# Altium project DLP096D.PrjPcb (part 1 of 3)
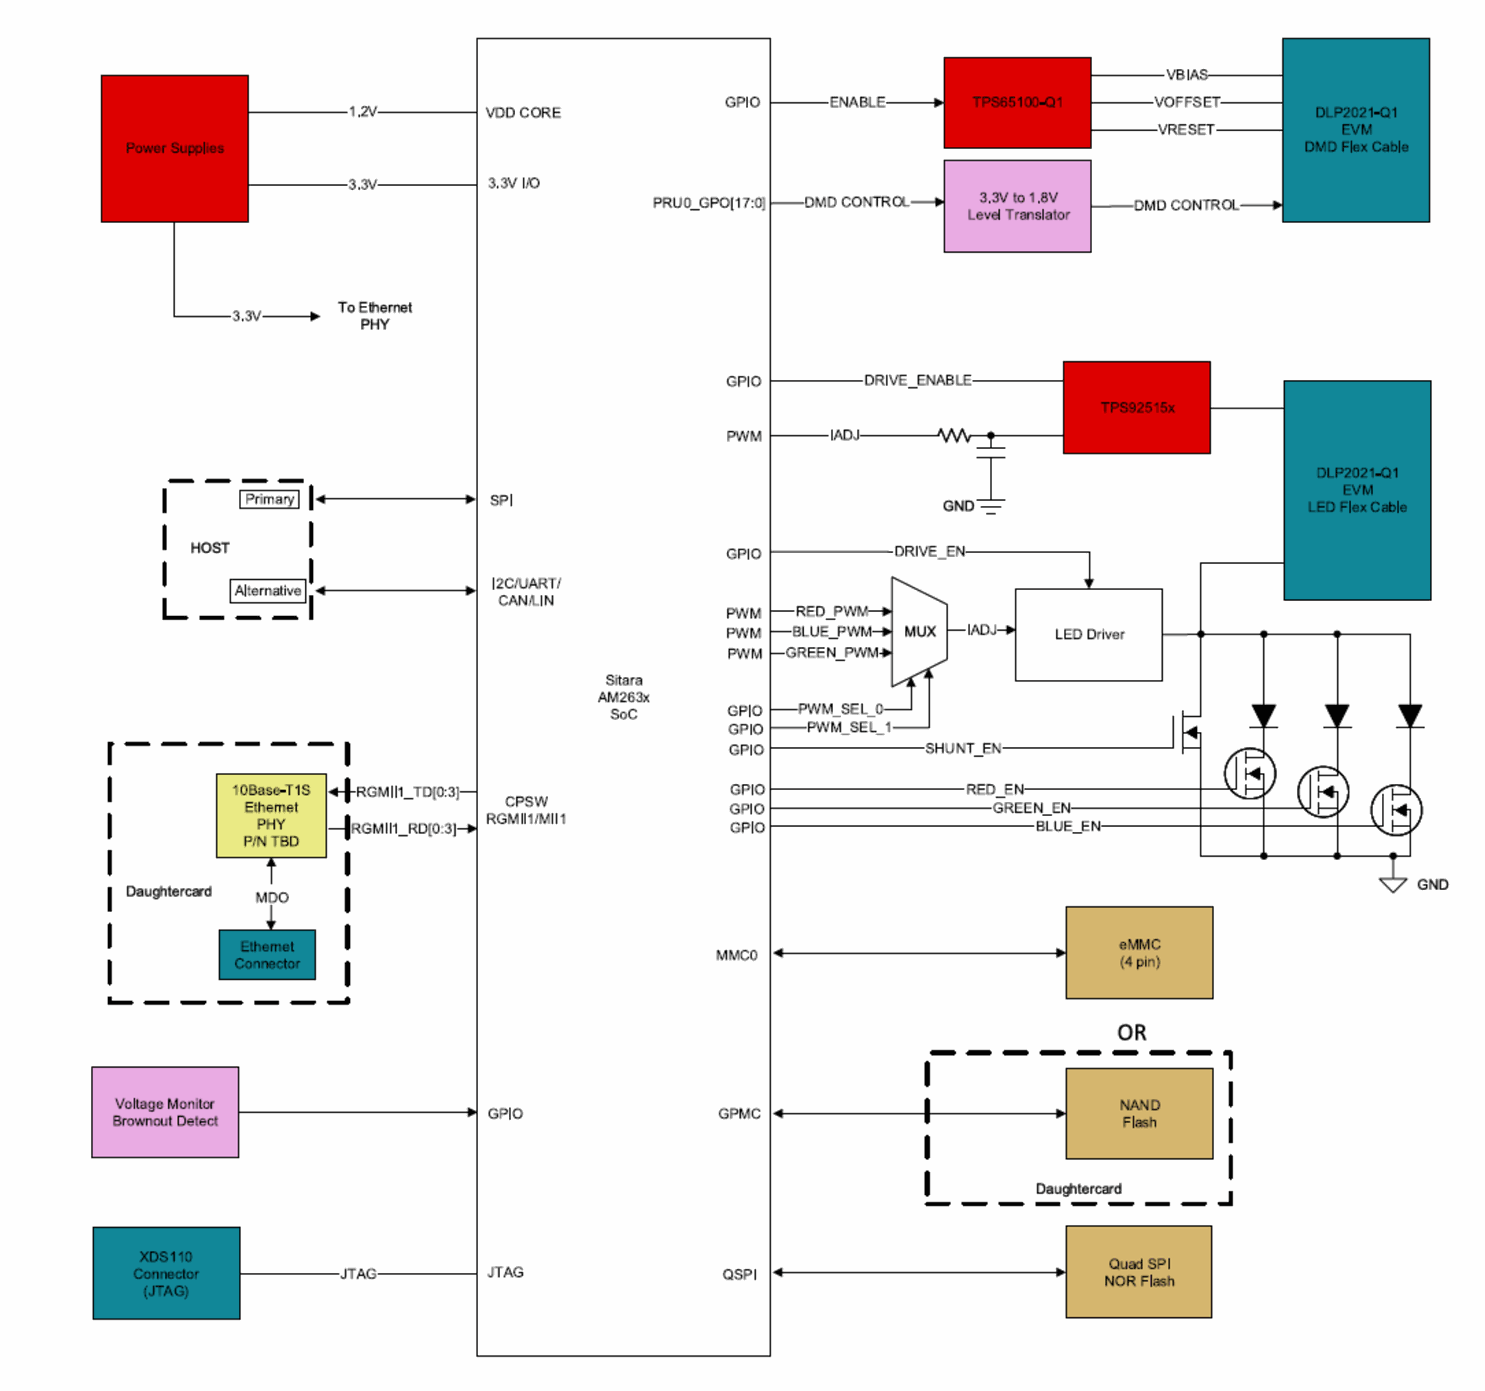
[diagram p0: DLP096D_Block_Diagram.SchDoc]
TID: N/A; TechSupport: http://www.ti.com/support; SCH_Rev: D; PRJ_Title: DLP2021AM263Q1EVM; PRJ_Number: DLP096; PRJ_Engineer: A. Whitehead; PRJ_Customer: Public Release; PCB_Rev: D; PCB_Layout: A. Whitehead; EVM_Orderable: DLP2021AM263Q1EVM; DrawnByGlobal: A. Whitehead; CopyrightYear: 2026
10 sheets, 329 parts. Net scope: global (net labels, ports and power ports of the same name join across sheets).
Board file: DLP096D.PcbDoc
Sheets:
  DLP096D_Block_Diagram.SchDoc
  DLP096D_Power_Tree.SchDoc
  DLP096D_System_Power.SchDoc
  DLP096D_SoC_Power_Clock.SchDoc
  DLP096D_DMD_Power.SchDoc
  DLP096D_DMD_Interface.SchDoc
  DLP096D_SoC_Memory.SchDoc
  DLP096D_Interfaces_Sockets.SchDoc
  DLP096D_LED_Driver.SchDoc
  DLP096D_Hardware.SchDoc

## Sheet DLP096D_Block_Diagram.SchDoc: Block Diagram
size 431 x 279 mm; Date: Not shown in title block; ApprovedBy: Not shown in title block; CheckedBy: Not shown in title block; Author: Not shown in title block; CompanyName: Not shown in title block; DrawnBy: A. Whitehead; Engineer: Not shown in title block; Organization: Not shown in title block; Address1: Not shown in title block; Address2: Not shown in title block; Address3: Not shown in title block; Address4: Not shown in title block; DocumentNumber: 1; Revision: Use project parameter SCH_Rev; SheetNumber: 1; SheetTotal: 10; PageSetup: Record=PageOptions¦CenterHorizontal=True¦CenterVertical=True¦PrintScale=1.00¦XCorrection=1.00¦YCorrection=1.00¦PrintKind=0¦BorderSize=5000000¦LeftOffset=0¦BottomOffset=0¦Orientation=2¦PaperLength=1000¦PaperWidth=1000¦Scale=100¦PaperSource=15¦PrintQuality=600¦MediaType=1¦DitherType=10¦PaperKind=Letter¦PrintScaleMode=1

## Sheet DLP096D_Power_Tree.SchDoc: Power Tree
size 431 x 279 mm; Date: Not shown in title block; ApprovedBy: Not shown in title block; CheckedBy: Not shown in title block; Author: Not shown in title block; CompanyName: Not shown in title block; DrawnBy: A. Whitehead; Engineer: Not shown in title block; Organization: Not shown in title block; Address1: Not shown in title block; Address2: Not shown in title block; Address3: Not shown in title block; Address4: Not shown in title block; DocumentNumber: 2; Revision: Use project parameter SCH_Rev; SheetNumber: 2; SheetTotal: 10; PageSetup: Record=PageOptions¦CenterHorizontal=True¦CenterVertical=True¦PrintScale=1.00¦XCorrection=1.00¦YCorrection=1.00¦PrintKind=0¦BorderSize=5000000¦LeftOffset=0¦BottomOffset=0¦Orientation=2¦PaperLength=1000¦PaperWidth=1000¦Scale=100¦PaperSource=15¦PrintQuality=600¦MediaType=1¦DitherType=10¦PaperKind=Letter¦PrintScaleMode=1
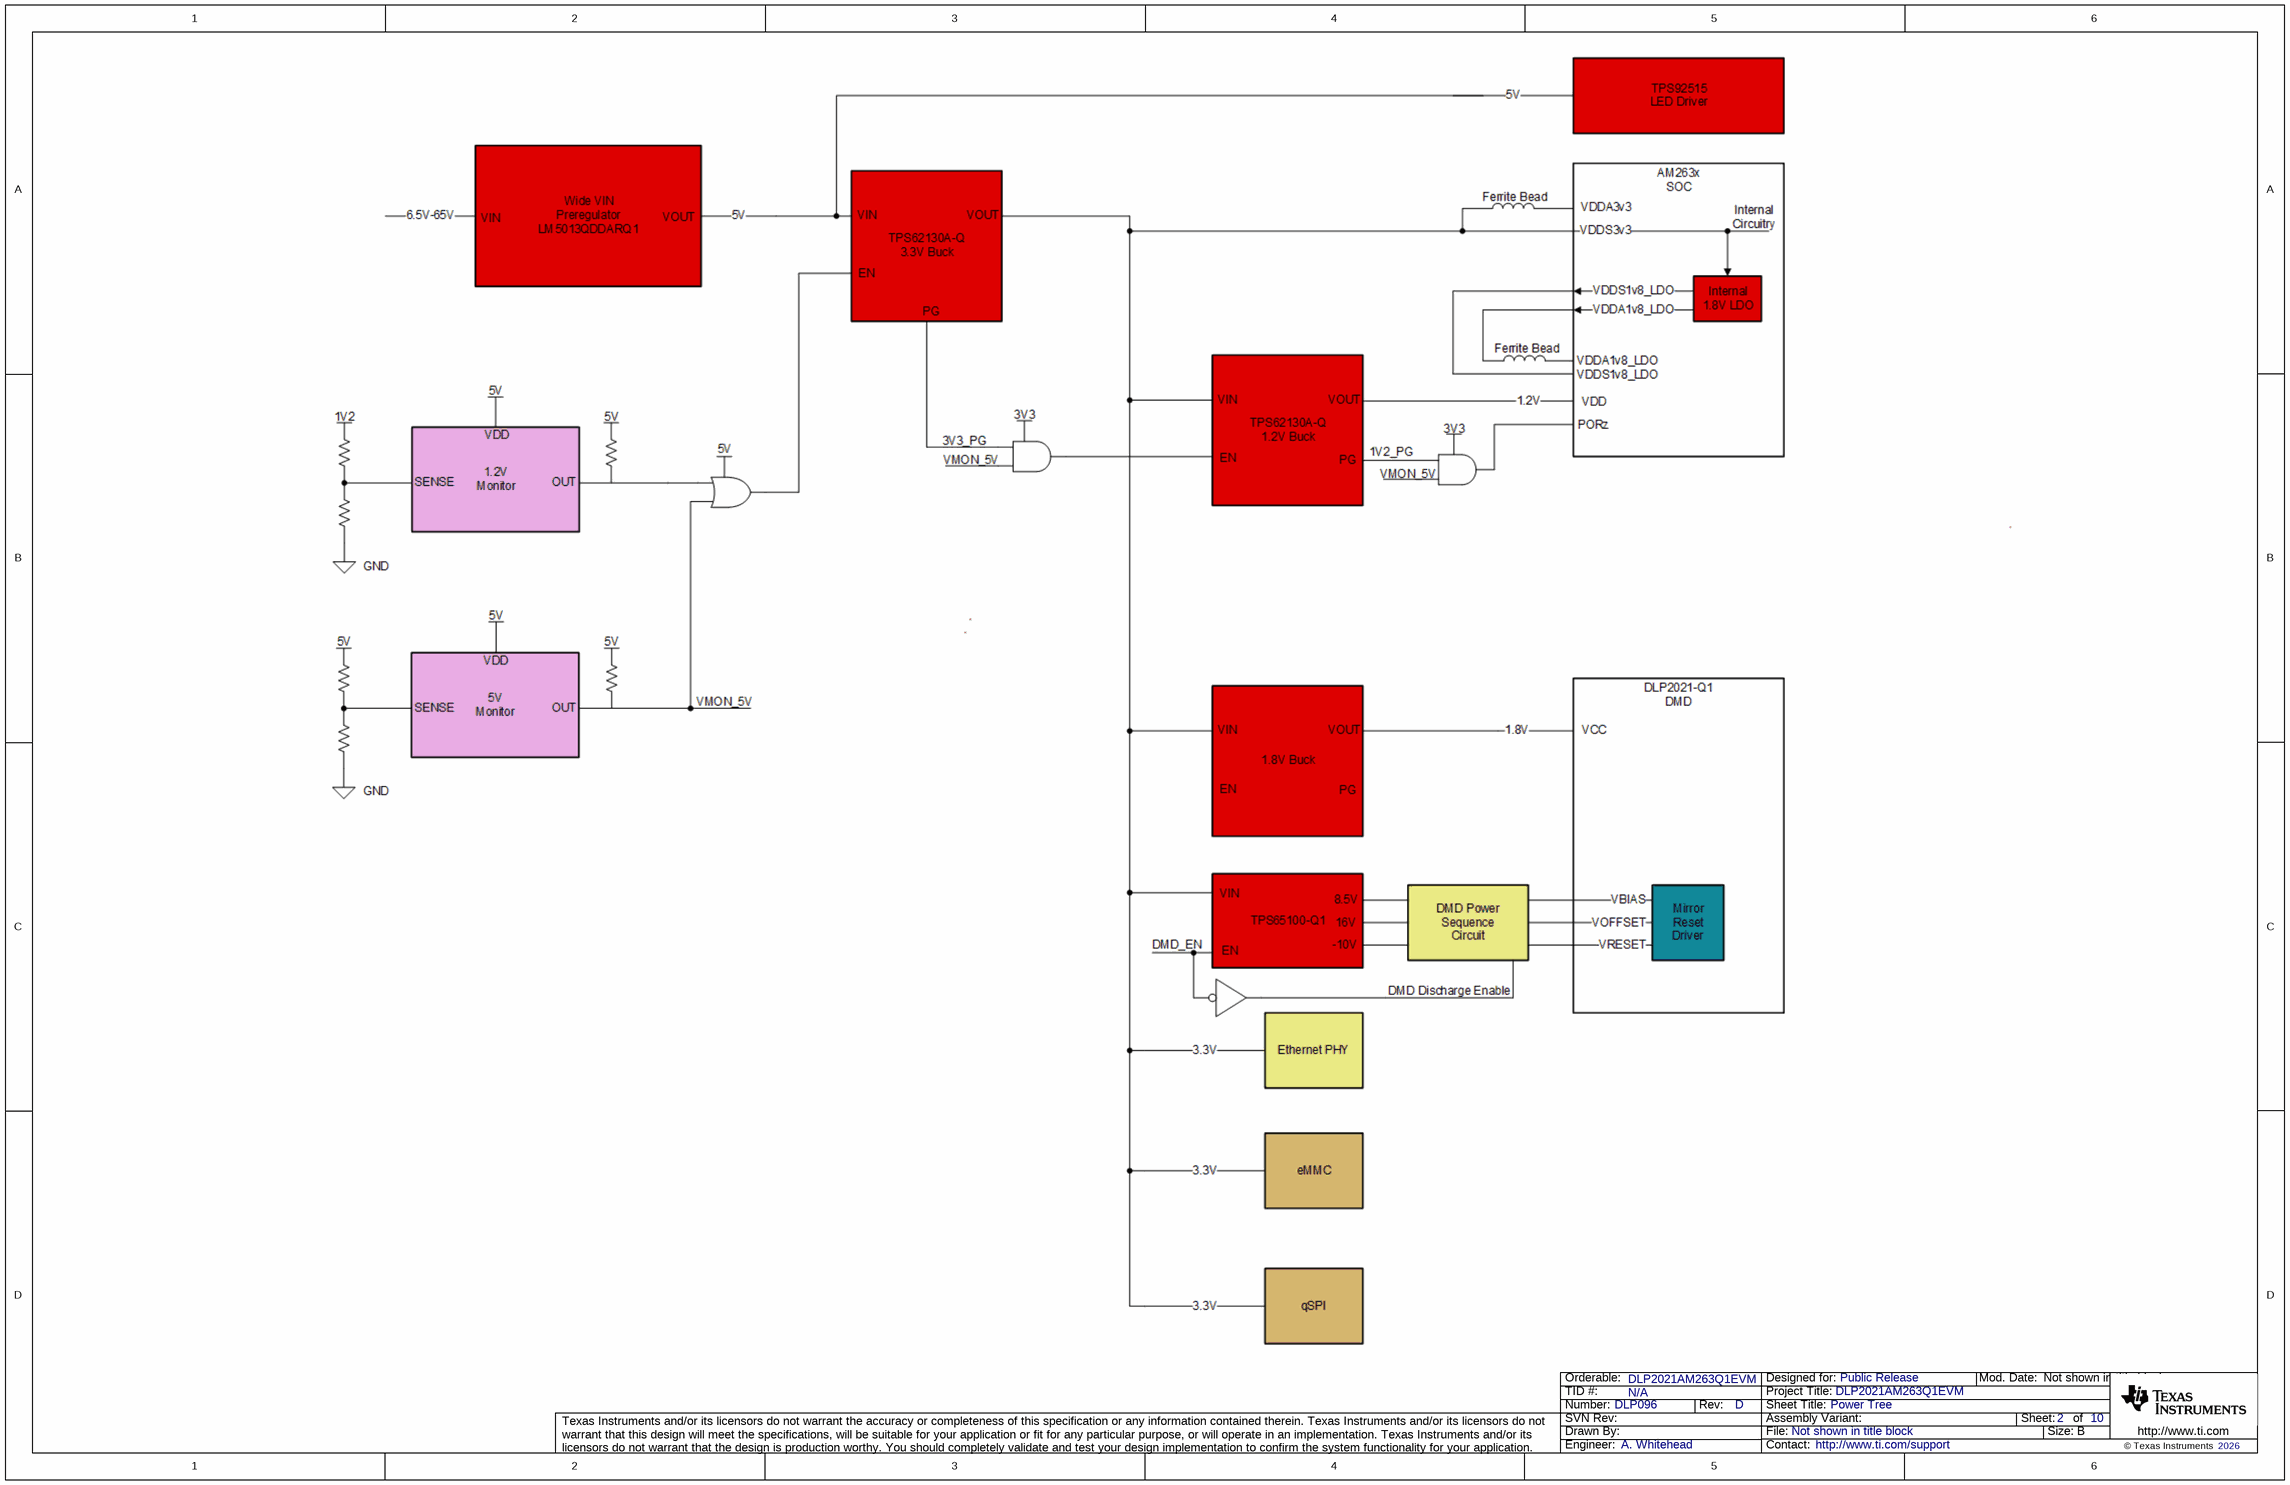
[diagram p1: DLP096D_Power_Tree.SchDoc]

## Sheet DLP096D_System_Power.SchDoc: System_Power
size 431 x 279 mm; Date: Not shown in title block; ApprovedBy: Not shown in title block; CheckedBy: Not shown in title block; Author: Not shown in title block; CompanyName: Not shown in title block; DrawnBy: A. Whitehead; Engineer: Not shown in title block; Organization: Not shown in title block; Address1: Not shown in title block; Address2: Not shown in title block; Address3: Not shown in title block; Address4: Not shown in title block; DocumentNumber: 3; Revision: Use project parameter SCH_Rev; SheetNumber: 3; SheetTotal: 10; PageSetup: Record=PageOptions¦CenterHorizontal=True¦CenterVertical=True¦PrintScale=1.00¦XCorrection=1.00¦YCorrection=1.00¦PrintKind=0¦BorderSize=5000000¦LeftOffset=0¦BottomOffset=0¦Orientation=2¦PaperLength=1000¦PaperWidth=1000¦Scale=100¦PaperSource=15¦PrintQuality=600¦MediaType=1¦DitherType=10¦PaperKind=Letter¦PrintScaleMode=1
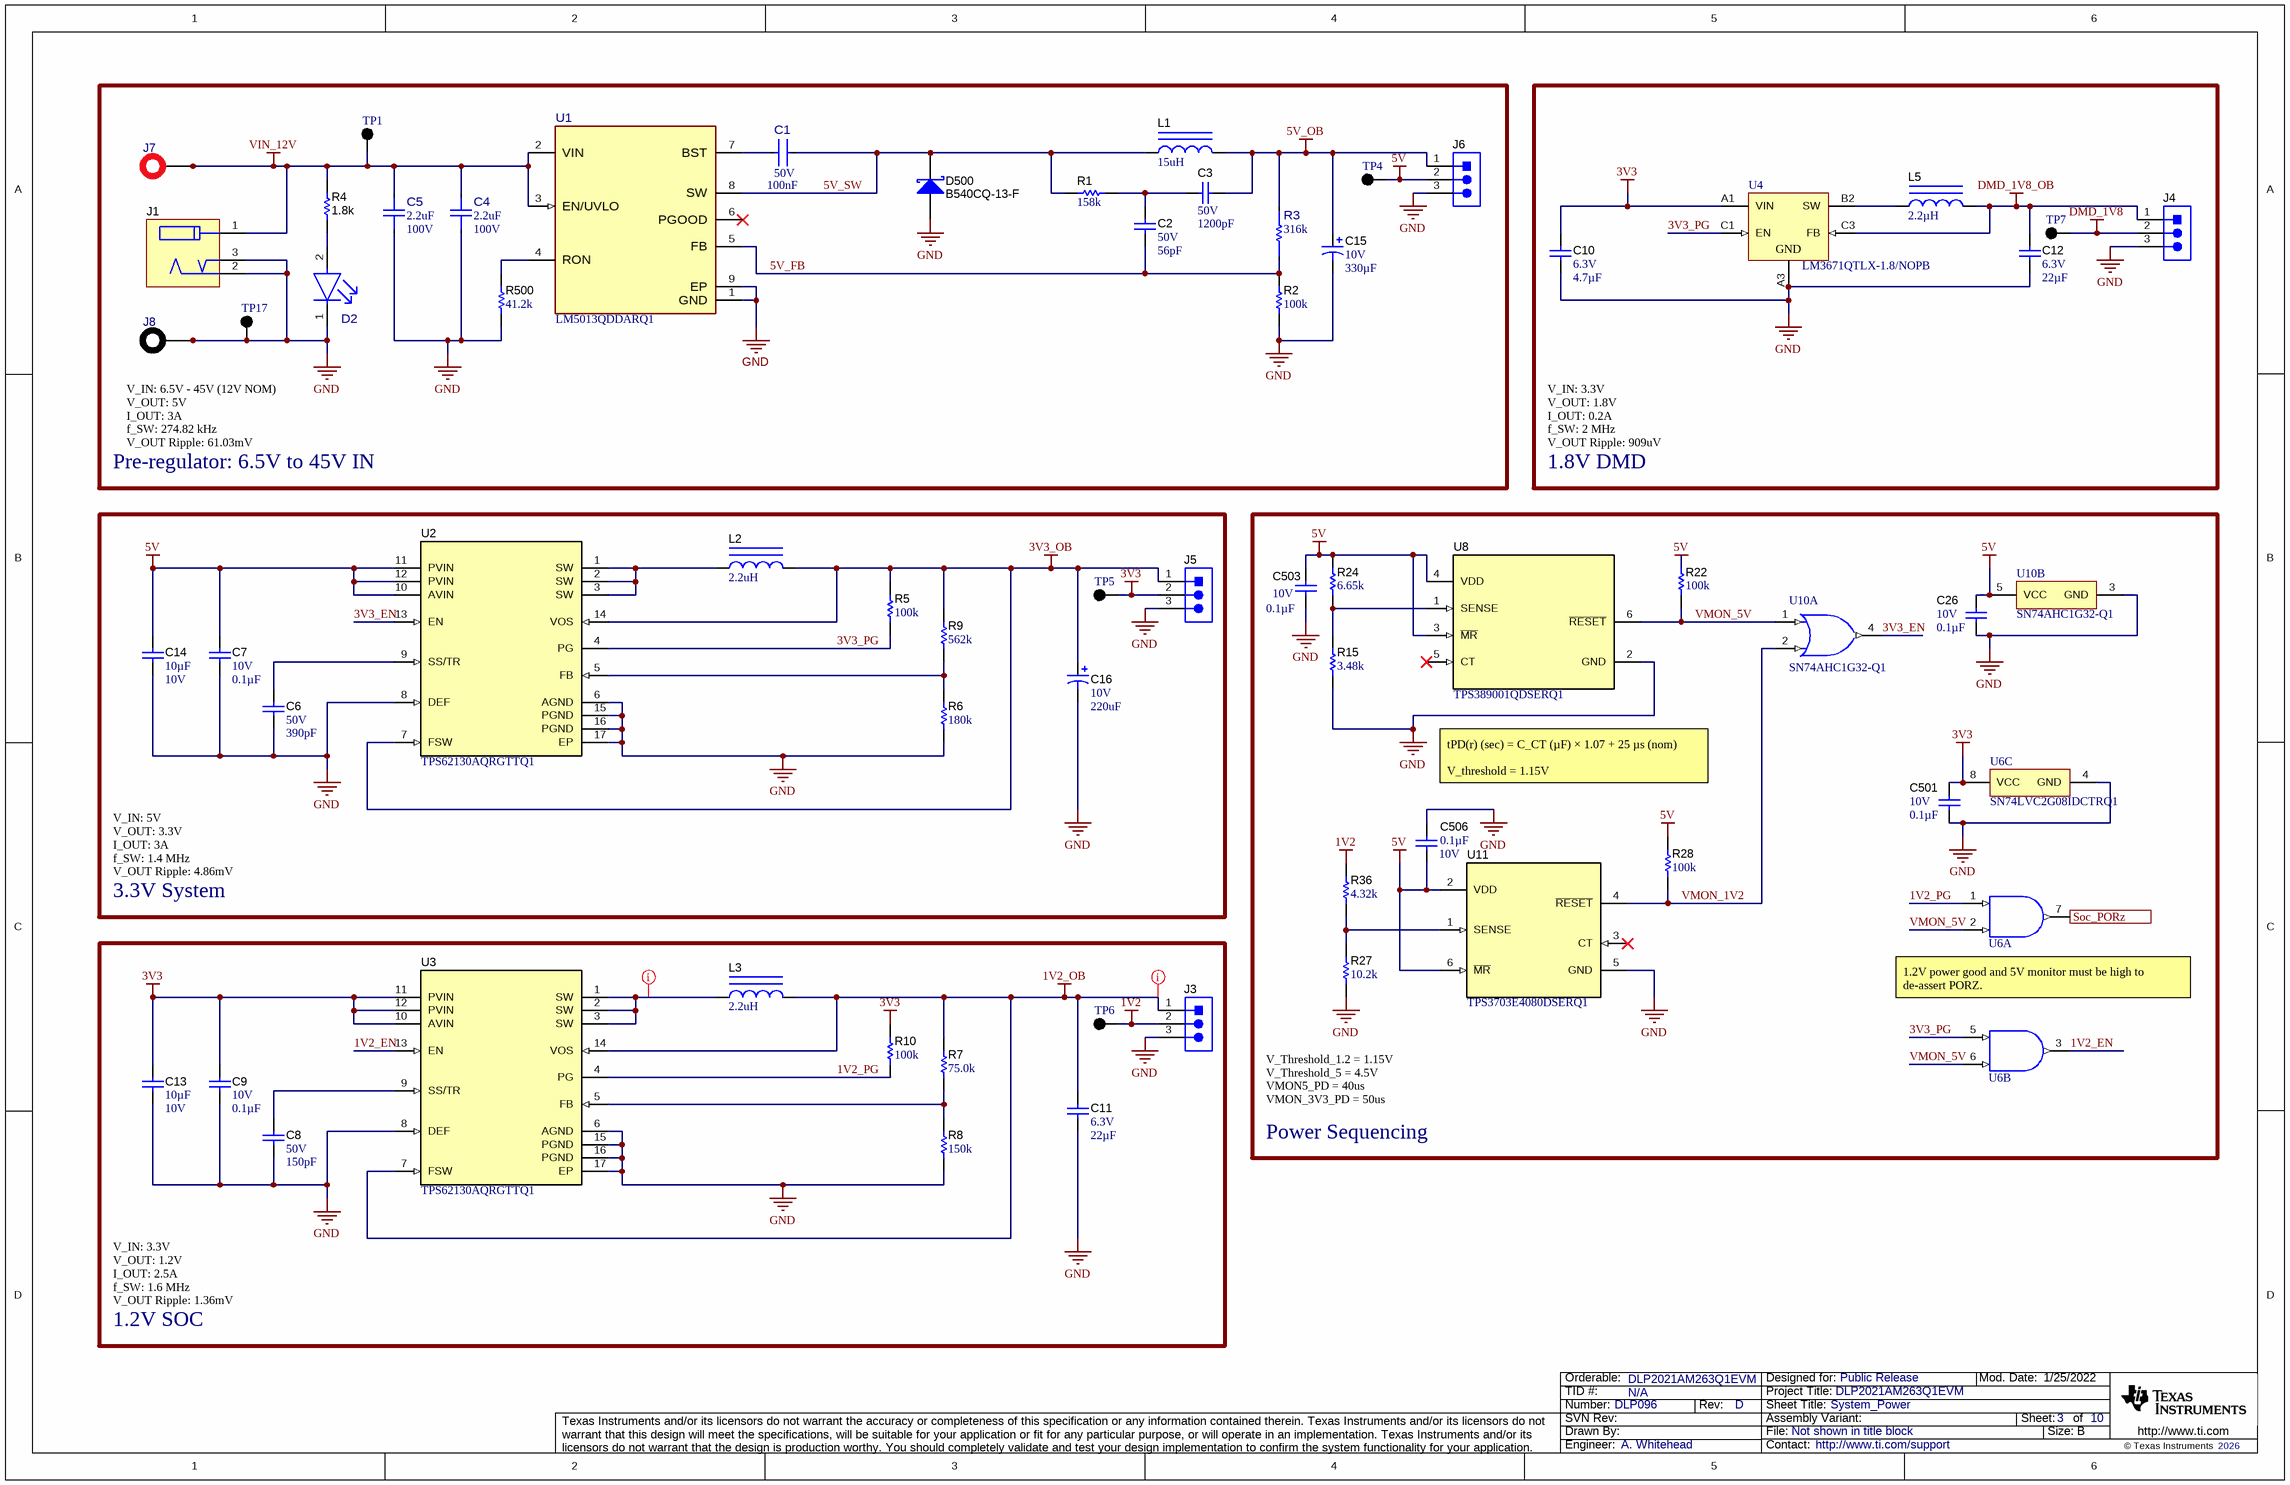
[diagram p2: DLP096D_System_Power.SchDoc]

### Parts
C1  Cap_F: 100nF  VDC_V: 50V  [FP-GCM188L81H104KA57D_0603-MFG]  (hidden comment: GCM188L81H104KA57D)
C2  VDC_V: 50V  ValueDisplayed: 56pF  [0603]  (hidden comment: 06035A560FAT2A)
C3  VDC_V: 50V  ValueDisplayed: 1200pF  [0603]  (hidden comment: GRM1885C1H122JA01D)
C4  ValueDisplayed: 2.2uF  VDC_V: 100V  [FP-GCJ32DL8EL225KA07L_1210-MFG]  (hidden comment: GCJ32DL8EL225KA07L)
C5  ValueDisplayed: 2.2uF  VDC_V: 100V  [FP-GCJ32DL8EL225KA07L_1210-MFG]  (hidden comment: GCJ32DL8EL225KA07L)
C6  VDC_V: 50V  ValueDisplayed: 390pF  [0402]  (hidden comment: GCM155R71H391KA37D)
C7  VDC_V: 10V  ValueDisplayed: 0.1µF  [0402]  (hidden comment: C0402C104K8RACTU)
C8  VDC_V: 50V  ValueDisplayed: 150pF  [0402]  (hidden comment: CGA2B2C0G1H151J050BA)
C9  VDC_V: 10V  ValueDisplayed: 0.1µF  [0402]  (hidden comment: C0402C104K8RACTU)
C10  VDC_V: 6.3V  ValueDisplayed: 4.7µF  [0402]  (hidden comment: GRM155R60J475ME47J)
C11  VDC_V: 6.3V  ValueDisplayed: 22µF  [0603]  (hidden comment: GRM186R60J226ME15D)
C12  VDC_V: 6.3V  ValueDisplayed: 22µF  [0603]  (hidden comment: GRM186R60J226ME15D)
C13  ValueDisplayed: 10µF  VDC_V: 10V  [0805_HV]  (hidden comment: CC0805ZKY5V6BB106)
C14  ValueDisplayed: 10µF  VDC_V: 10V  [0805_HV]  (hidden comment: CC0805ZKY5V6BB106)
C15  VDC_V: 10V  ValueDisplayed: 330µF  [CL_800x1000]  (hidden comment: UCL1A331MNL1GS)
C16  VDC_V: 10V  ValueDisplayed: 220uF  [SM_RADIAL_6.3BMM]  (hidden comment: UUD1A221MCL1GS)
C26  VDC_V: 10V  ValueDisplayed: 0.1µF  [0402]  (hidden comment: C0402C104K8RACTU)
C501  VDC_V: 10V  ValueDisplayed: 0.1µF  [0402]  (hidden comment: C0402C104K8RACTU)
C503  VDC_V: 10V  ValueDisplayed: 0.1µF  [0402]  (hidden comment: C0402C104K8RACTU)
C506  VDC_V: 10V  ValueDisplayed: 0.1µF  [0402]  (hidden comment: C0402C104K8RACTU)
D2  LSL29K-G1H2-1-Z  [FP-LSL29K-G1H2-1-Z_0603-0]  (value not drawn)
D500  B540CQ-13-F  [SMC]
J1  EJ508A  [Memory_EJ508A]  (value not drawn)
J3  22284033  [Molex_0022284033]  (value not drawn)
J4  22284033  [Molex_0022284033]  (value not drawn)
J5  22284033  [Molex_0022284033]  (value not drawn)
J6  22284033  [Molex_0022284033]  (value not drawn)
J7  571-0500  [571-0500]  (value not drawn)
J8  571-0100  [571-0100]  (value not drawn)
L1  ValueDisplayed: 15uH  [MSS1210]  (hidden comment: MSS1210-153ME)
L2  ValueDisplayed: 2.2uH  [XAL5030]  (hidden comment: XAL5030-222MEB)
L3  ValueDisplayed: 2.2uH  [XAL5030]  (hidden comment: XAL5030-222MEB)
L5  ValueDisplayed: 2.2µH  [0805_HV]  (hidden comment: MLP2012V2R2MT0S1)
R1  ValueDisplayed: 158k  [0603]  (hidden comment: CRCW0603158KFKEA)
R2  ValueDisplayed: 100k  [0603]  (hidden comment: CRCW0603100KFKEA)
R3  value 316k  [FP-CR0603-FX-3163ELF_0603-MFG]  (hidden comment: CR0603-FX-3163ELF)
R4  ValueDisplayed: 1.8k  [0402L]  (hidden comment: CRCW04021K80JNED)
R5  ValueDisplayed: 100k  [0805_HV]  (hidden comment: ERJ-6ENF1003V)
R6  ValueDisplayed: 180k  [0603]  (hidden comment: RC0603FR-07180KL)
R7  ValueDisplayed: 75.0k  [0603]  (hidden comment: RC0603FR-0775KL)
R8  ValueDisplayed: 150k  [0603]  (hidden comment: RC0603FR-07150KL)
R9  ValueDisplayed: 562k  [0603]  (hidden comment: RC0603FR-07562KL)
R10  ValueDisplayed: 100k  [0805_HV]  (hidden comment: ERJ-6ENF1003V)
R15  ValueDisplayed: 3.48k  [1206]  (hidden comment: ERJ-8ENF3481V)
R22  ValueDisplayed: 100k  [0805_HV]  (hidden comment: ERJ-6ENF1003V)
R24  ValueDisplayed: 6.65k  [0805_HV]  (hidden comment: ERJ-6ENF6651V)
R27  ValueDisplayed: 10.2k  [0805_HV]  (hidden comment: CRCW080510K2FKEA)
R28  ValueDisplayed: 100k  [0805_HV]  (hidden comment: ERJ-6ENF1003V)
R36  ValueDisplayed: 4.32k  [0603]  (hidden comment: RC0603FR-074K32L)
R500  ValueDisplayed: 41.2k  [0402]  (hidden comment: CRCW040241K2FKED)
TP1  5001  [Keystone5001]  (value not drawn)
TP4  5001  [Keystone5001]  (value not drawn)
TP5  5001  [Keystone5001]  (value not drawn)
TP6  5001  [Keystone5001]  (value not drawn)
TP7  5001  [Keystone5001]  (value not drawn)
TP17  5001  [Keystone5001]  (value not drawn)
U1  LM5013QDDARQ1  [DDA0008E-MFG]
U2  TPS62130AQRGTTQ1  [RGT0016C]
U3  TPS62130AQRGTTQ1  [RGT0016C]
U4  PartNumber: LM3671QTLX-1.8/NOPB  [YZR0005AEBA]  (hidden comment: LM3671TLX-1.8/NOPB)
U6  SN74LVC2G08IDCTRQ1  [DCT0008A_N]  (value not drawn)  (parts A,B,C of 3)
U8  TPS389001QDSERQ1  [DSE0006A]
U10  Generic Part Number: SN74AHC1G32-Q1  [DBV0005A_N]  (hidden comment: SN74AHC1G32TDBVRQ1)  (parts A,B of 2)
U11  TPS3703E4080DSERQ1  [DSE0006A]

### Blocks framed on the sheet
Pre-regulator: 6.5V to 45V IN: C1-C5 C15 D2 D500 J1 J6-J8 L1 R1-R4 R500 TP1 TP4 TP17 U1
1.8V DMD: C10 C12 J4 L5 TP7 U4
3.3V System: C6 C7 C14 C16 J5 L2 R5 R6 R9 TP5 U2
Power Sequencing: C26 C501 C503 C506 R15 R22 R24 R27 R28 R36 U6 U8 U10 U11
1.2V SOC: C8 C9 C11 C13 J3 L3 R7 R8 R10 TP6 U3

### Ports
Soc_PORz (out)

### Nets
1V2: J3.2 R36.2 TP6.1  [project net VDDAR]
1V2_OB: C11.1 J3.1 L3.2 R7.2 U3.7(FSW) U3.14(VOS)
3V3: C9.1 C10.1 C13.1 C501.1 J5.2 R10.2 TP5.1 U3.10(AVIN) U3.11(PVIN) U3.12(PVIN) U4.A1(VIN) U6.8(VCC)  [project net VDDS33]
3V3_OB: C16.1(+) J5.1 L2.2 R5.2 R9.2 U2.7(FSW) U2.14(VOS)
5V: C7.1 C14.1 C26.1 C503.1 C506.1 J6.2 R22.2 R24.2 R28.2 TP4.1 U2.10(AVIN) U2.11(PVIN) U2.12(PVIN) U8.3(~{MR}) U8.4(VDD) U10.5(VCC) U11.2(VDD) U11.6(~{MR})
5V_OB: C3.1 C15.1(+) J6.1 L1.2 R3.2
DMD_1V8: J4.2 TP7.1
DMD_1V8_OB: C12.1 J4.1 L5.2 U4.C3(FB)
GND: C4.1 C5.1 C6.2 C7.2 C8.2 C9.2 C10.2 C11.2 C12.2 C13.2 C14.2 C15.2(-) C16.2(-) C26.2 C501.2 C503.2 C506.2 D2.1(CATHODE) D500.2(A) J1.2 J1.3 J3.3 J4.3 J5.3 J6.3 J8.1 J8.2 R2.1 R6.1 R8.1 R15.1 R27.1 R500.1 TP17.1 U1.1(GND) U1.9(EP) U2.6(AGND) U2.8(DEF) U2.15(PGND) U2.16(PGND) U2.17(EP) U3.6(AGND) U3.8(DEF) U3.15(PGND) U3.16(PGND) U3.17(EP) U4.A3(GND) U6.4(GND) U8.2(GND) U10.3(GND) U11.5(GND)
VIN_12V: C4.2 C5.2 J1.1 J7.1 J7.2 R4.2 TP1.1 U1.2(VIN) U1.3(EN/UVLO)
1V2_EN: U3.13(EN) U6.3(2Y)
1V2_PG: R10.1 U3.4(PG) U6.1(1A)
3V3_EN: U2.13(EN) U10.4(Y)
3V3_PG: R5.1 U2.4(PG) U4.C1(EN) U6.5(2A)
5V_FB: C2.2 R2.2 R3.1 U1.5(FB)
5V_SW: C1.2 D500.1(K) L1.1 R1.1 U1.8(SW)
Soc_PORz: U6.7(1Y) ; port Soc_PORz
VMON_1V2: R28.1 U10.2(B) U11.4(~{RESET})
VMON_5V: R22.1 U6.2(1B) U6.6(2B) U8.6(~{RESET}) U10.1(A)
NetC1_1: C1.1 U1.7(BST)
NetC2_1: C2.1 C3.2 R1.2
NetC6_1: C6.1 U2.9(SS/TR)
NetC8_1: C8.1 U3.9(SS/TR)
NetD2_2: D2.2(ANODE) R4.1
NetL2_1: L2.1 U2.1(SW) U2.2(SW) U2.3(SW)
NetL3_1: L3.1 U3.1(SW) U3.2(SW) U3.3(SW)
NetL5_1: L5.1 U4.B2(SW)
NetR6_2: R6.2 R9.1 U2.5(FB)
NetR7_1: R7.1 R8.2 U3.5(FB)
NetR15_2: R15.2 R24.1 U8.1(SENSE)
NetR27_2: R27.2 R36.1 U11.1(SENSE)
NetR500_2: R500.2 U1.4(RON)

Not connected (* = marked no-connect by the designer): U1 6(PGOOD)*; U8 5(CT)*; U11 3(CT)*

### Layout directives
net class POWER; net class Voltage: 1V2_OB, NetL3_1

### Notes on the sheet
- V_IN: 6.5V - 45V (12V NOM)
  V_OUT: 5V
  I_OUT: 3A
  f_SW: 274.82 kHz
  V_OUT Ripple: 61.03mV
- V_IN: 3.3V
  V_OUT: 1.8V
  I_OUT: 0.2A
  f_SW: 2 MHz
  V_OUT Ripple: 909uV
- tPD(r) (sec) = C_CT (µF) × 1.07 + 25 µs (nom)
  V_threshold = 1.15V
- V_IN: 5V
  V_OUT: 3.3V
  I_OUT: 3A
  f_SW: 1.4 MHz
  V_OUT Ripple: 4.86mV
- (near U6) 1.2V power good and 5V monitor must be high to de-assert PORZ.
- V_Threshold_1.2 = 1.15V
  V_Threshold_5 = 4.5V
  VMON5_PD = 40us
  VMON_3V3_PD = 50us
- V_IN: 3.3V
  V_OUT: 1.2V
  I_OUT: 2.5A
  f_SW: 1.6 MHz
  V_OUT Ripple: 1.36mV

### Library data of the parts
C1 = CMP-0086535-1: 0.1µF ±10% 50V Ceramic Capacitor X8L 0603 (1608 Metric); Manufacturer: Murata Electronics North America; Symbol Name: SYM-GCM188L81H104KA57D; AEC Qualified: Yes; TempCo: -40+15%; SizeZ_mm: 0.9mm; AEC Grade: Grade 0
C2 = CMP-0006792-3: CAP, CERM, 56 pF, 50 V, +/- 1%, C0G/NP0, 0603; Manufacturer: AVX; TaMin_C: -55°C; Polarized: N; SizeAreaWB_mm2: 4.68; Value1: Unknown; U/M: EA; Value: 56pF; TaMax_C: 125°C; SizeZ_mm: 1; SizeX_mm: 1.6; SizeY_mm: 0.8; SizeArea_mm2: 1.28; AEC Category: Q200
C3 = CMP-0007180-1: CAP, CERM, 1200 pF, 50 V, +/- 5%, C0G/NP0, 0603; Manufacturer: MuRata; TaMin_C: -55°C; Polarized: N; SizeAreaWB_mm2: 4.68; Value1: Unknown; U/M: EA; Value: 1200pF; TaMax_C: 125°C; SizeZ_mm: 1; SizeX_mm: 1.6; SizeY_mm: 0.8; SizeArea_mm2: 1.28; Cap_F: 1.2nF; AEC Category: Q200
C4 C5 = CMP-0089367-1: 2.2µF ±10% 100V Ceramic Capacitor X8L 1210 (3225 Metric); Manufacturer: Murata; TempCo: +15/-40%; AEC Qualified: Yes; AEC Grade: Grade 0; SizeZ_mm: 2.3mm
C6 = CMP-0080703-2: CAP, CERM, 390 pF, 50 V,+/- 10%, X7R, AEC-Q200 Grade 1, 0402; Manufacturer: MuRata; SizeX_mm: 1; SizeZ_mm: 0.6; SizeY_mm: 0.5; AEC Qualified: Y; Value: 390pF; Polarized: N; AEC Category: Q200; TaMax_C: 125°C; TaMin_C: -55°C; SizeAreaWB_mm2: 3; U/M: EA
C7 C9 C26 C501 C503 C506 = CMP-0078241-1: CAP, CERM, 0.1 µF, 10 V,+/- 10%, X7R, 0402; Manufacturer: Kemet; TaMin_C: -55°C; Polarized: N; SizeAreaWB_mm2: 3; U/M: EA; Value: 0.1uF; TaMax_C: 125°C; SizeZ_mm: 0.6; SizeX_mm: 1; SizeY_mm: 0.5; Cap_F: 100nF; AEC Category: Q200
C8 = CMP-0006310-2: CAP, CERM, 150 pF, 50 V, +/- 5%, C0G/NP0, AEC-Q200 Grade 1, 0402; Manufacturer: TDK; TaMin_C: -55°C; Polarized: N; SizeAreaWB_mm2: 3; Value1: Unknown; U/M: EA; Value: 150pF; TaMax_C: 125°C; SizeZ_mm: 0.6; SizeX_mm: 1; SizeY_mm: 0.5; AEC Qualified: Y; AEC Category: Q200
C10 = CMP-0080385-1: CAP, CERM, 4.7 µF,  VAC/6.3 VDC,+/- 20%, X5R, 0402; Manufacturer: MuRata; TaMin_C: -55°C; ESR_ohm: 1m; Polarized: N; SizeAreaWB_mm2: 3; Value1: 0.001 ohm; U/M: EA; Value: 4.7uF; TaMax_C: 85°C; SizeZ_mm: 0.6; SizeX_mm: 1; SizeY_mm: 0.5; AEC Category: Q200
C11 C12 = CMP-0078295-1: CAP, CERM, 22 µF, 6.3 V,+/- 20%, X5R, 0603; Manufacturer: MuRata; TaMin_C: -55°C; Polarized: N; SizeAreaWB_mm2: 4.68; U/M: EA; Value: 22uF; TaMax_C: 85°C; SizeZ_mm: 1; SizeX_mm: 1.6; SizeY_mm: 0.8; SizeArea_mm2: 1.28; AEC Category: Q200
C13 C14 = CMP-0085574-1: CAP, CERM, 10 µF, 10 V,+80/-20%, Y5V, 0805; Manufacturer: Yageo; AEC Category: Q200; Cap_Case: 0805; SizeY_mm: 1.25; AEC Qualified: N; SizeX_mm: 2; Tolerance_%: 80%; TaMax_C: 85°C; TaMin_C: -30°C; Green_Lifecycle: Active; Green_REACh: Incomplete; Value: 10uF; U/M: EA; SizeAreaWB_mm2: 6.75; SizeZ_mm: 1.45; SizeArea_mm2: 2.5
C15 = CMP-0081924-1: CAP, AL, 330 µF, 10 V, +/- 20%, SMD; Manufacturer: Nichicon; IRMS_A: 850mA; SizeZ_mm: 10.5; AEC Qualified: N; Value: 330uF; TaMin_C: -55°C; Polarized: Y; SizeAreaWB_mm2: 112.27; U/M: EA; TaMax_C: 105°C; SizeX_mm: 8.9; SizeY_mm: 8.3; Cap_Case: 8x10mm; SizeArea_mm2: 73.87; CompType: Capacitor; AEC Category: Q200
C16 = CMP-0011112-1: CAP, AL, 220 uF, 10 V, +/- 20%, 0.34 ohm, SMD; Manufacturer: Nichicon; TaMin_C: -55°C; Polarized: Y; SizeAreaWB_mm2: 79.98; U/M: EA; Value: 220uF; TaMax_C: 105°C; SizeZ_mm: 7.7; SizeX_mm: 7.3; SizeY_mm: 6.6; Cap_Case: 6.3x7.7; SizeArea_mm2: 48.18; CompType: Capacitor; Cap_F: 220µF; AEC Category: Q200; ESR_ohm: 0.34; IRMS_A: 280mA
D2 = CMP-0092845-1: LED Uni-Color Red 643nm 2-Pin Chip 0603(1608Metric) T/R; Manufacturer: OSRAM Opto Semiconductors; AEC Grade: Grade 2; LuminousFlux_PhiV: 8.1/16.1lm; Vf_V: 1.8V; Forward Current: 2mA; Led Orientation: Top View; SizeZ_mm: 0.67mm; AEC Qualified: Yes; Luminous Intensity: 1.8-2.24/3.55-4.5mcd; Vr_V: 12V; Angle: 160°; LambdaD: 630nm; Tjmax_C: 110°C
D500 = CMP-0077948-2: Diode, Schottky, 40 V, 5 A, AEC-Q101, SMC; Manufacturer: Diodes Inc.; AEC Category: Q101; SizeAreaWB_mm2: 83.2686; SizeX_mm: 8.13; Vf_V: 550mV; TJmax_C: 150°C; RJC_CperW: 10; Vr_V: 40V; SizeZ_mm: 2.6; AEC Qualified: Y; Value1: 5A; Value: 40V; Value2: 0.55V; SizeArea_mm2: 50.5686; SizeY_mm: 6.22
J1 = CMP-0055800-1: Power Jack, 2.1x5.5mm, R/A, TH; Manufacturer: Memory Protection Devices; CNHeader: FALSE; Current_A: 5A; Gender: Male; Voltage_V: 12V
J3-J6 = CMP-0055332-1: Header, 2.54mm, 3x1, Tin, TH; Manufacturer: Molex; CNHeader: TRUE; Current_A: 4A; Shrouded: N; Gender: Male; Voltage_V: 250V; Row_Count: 1; Pitch_mm: 2.54; CT: FALSE; Cert_UL: Y
J7 = CMP-0055393-3: Standard Banana Jack, insulated, 10A, red; Manufacturer: DEM Manufacturing; Green_REACh: Incomplete; Green_Lifecycle: Not Set
J8 = CMP-0055389-3: Standard Banana Jack, insulated, 10A, black; Manufacturer: DEM Manufacturing; Green_REACh: Incomplete; Green_Lifecycle: Not Set
L1 = CMP-0061454-2: Inductor, Shielded, Ferrite, 15 uH, 8.7 A, 0.019 ohm, SMD; Manufacturer: Coilcraft; Isat: 10.7A @ 30% inductance drop; Irms: 8.7A @ 40C rise; Green_Lifecycle: Not Set; SizeAreaWB_mm2: 204.49; DCR_ohm: 19m; Green_REACh: Incomplete; Value: 15uH; Imax_A: 8.7A; SizeZ_mm: 10; SizeX_mm: 12.3; SizeArea_mm2: 151.29; Ind_H: 15µH; AEC Category: Q200
L2 L3 = CMP-0061001-2: Inductor, Shielded, Composite, 2.2 µH, 9.2 A, 0.01 ohm, AEC-Q200 Grade 1, SMD; Manufacturer: Coilcraft; Isat: 12.9A @ 30% inductance drop; Irms: 9.2A @ 40C rise; Green_Lifecycle: Not Set; SizeAreaWB_mm2: 54.4544; DCR_ohm: 10m; Green_REACh: Incomplete; Value: 2.2uH; Imax_A: 9.2A; SizeZ_mm: 3.1; SizeX_mm: 5.28; SizeY_mm: 5.48; SizeArea_mm2: 28.9344; Ind_H: 2.2µH; AEC Qualified: 1; AEC Category: Q200; AEC Grade: Y
L5 = CMP-0082247-1: Inductor, Shielded, Ferrite, 2.2 µH, 0.7 A, 0.364 ohm, SMD; Manufacturer: TDK; Irms: 0.7A @ 40C rise; SizeAreaWB_mm2: 6.75; DCR_ohm: 0.364; Value: 2.2uH; Imax_A: 700mA; SizeZ_mm: 1.45; SizeX_mm: 2; SizeY_mm: 1.25; Value2: 0.7A; SizeArea_mm2: 2.5; AEC Qualified: N; AEC Category: Q200
R1 = CMP-0022064-1: RES, 158 k, 1%, 0.1 W, 0603; Manufacturer: Vishay-Dale; Power_W: 100mW; TempCo: 100 ppm/C; U/M: EA; Value: 158k; EIA_Code: E96; SizeX_mm: 1.6; SizeY_mm: 0.8; SizeZ_mm: 1; Value2: 0.1W; SizeArea_mm2: 1.28; VDC_V: 75V; AEC Category: Q200
R2 = CMP-0021990-4: RES, 100 k, 1%, 0.1 W, AEC-Q200 Grade 0, 0603; Manufacturer: Vishay-Dale; Power_W: 100mW; TempCo: 100 ppm/C; Value: 100k; EIA_Code: E96; SizeX_mm: 1.6; SizeY_mm: 0.8; SizeZ_mm: 1; Value2: 0.1W; SizeArea_mm2: 1.28; AEC Qualified: Y; VDC_V: 75V; AEC Category: Q200; AEC Grade: 0
R3 = CMP-0093627-1: Thick Film Chip Resistors 0603 316kΩ 0.1W 1% 100ppm/°C; Manufacturer: Bourns; AEC Qualified: No; SizeZ_mm: 0.55mm; Power_W: 100mW; VDC_V: 75V
R4 = CMP-0026858-5: RES, 1.8 k, 5%, 0.063 W, AEC-Q200 Grade 0, 0402; Manufacturer: Vishay-Dale; Power_W: 63mW; TempCo: 200 ppm/C; Value_Code: 1k80; Value: 1.8k; EIA_Code: E24; SizeX_mm: 1; SizeY_mm: 0.5; SizeZ_mm: 0.6; Value2: 0.063W; AEC Qualified: Y; VDC_V: 50V; AEC Category: Q200; AEC Grade: 0
R5 R10 R22 R28 = CMP-0021521-3: RES, 100 k, 1%, 0.125 W, AEC-Q200 Grade 0, 0805; Manufacturer: Panasonic; Power_W: 125mW; TempCo: 100 ppm/C; Value: 100k; EIA_Code: E96; SizeX_mm: 2; SizeY_mm: 1.25; SizeZ_mm: 1.45; Value2: 0.125W; SizeArea_mm2: 2.5; AEC Qualified: Y; AEC Category: Q200; AEC Grade: 0; SizeAreaWB_mm2: 6.75
R6 = CMP-0022844-4: RES, 180 k, 1%, 0.1 W, 0603; Manufacturer: Yageo; Power_W: 100mW; TempCo: 100 ppm/C; Value: 180k; SizeX_mm: 1.6; SizeY_mm: 0.8; SizeZ_mm: 1; Value2: 0.1W; SizeArea_mm2: 1.28; AEC Qualified: N; VDC_V: 75V; AEC Category: Q200; SizeAreaWB_mm2: 4.68
R7 = CMP-0023267-5: RES, 75.0 k, 1%, 0.1 W, 0603; Manufacturer: Yageo; Power_W: 100mW; TempCo: 100 ppm/C; Value_Code: 75k0; Value: 75.0k; EIA_Code: E96; Res_ohm: 75k; SizeX_mm: 1.6; SizeY_mm: 0.8; SizeZ_mm: 1; Value2: 0.1W; SizeArea_mm2: 1.28; AEC Qualified: N; VDC_V: 75V; AEC Category: Q200; SizeAreaWB_mm2: 4.68
R8 = CMP-0022808-4: RES, 150 k, 1%, 0.1 W, 0603; Manufacturer: Yageo; Power_W: 100mW; TempCo: 100 ppm/C; Value: 150k; EIA_Code: E96; SizeX_mm: 1.6; SizeY_mm: 0.8; SizeZ_mm: 1; Value2: 0.1W; SizeArea_mm2: 1.28; AEC Qualified: N; VDC_V: 75V; AEC Category: Q200; SizeAreaWB_mm2: 4.68
R9 = CMP-0023184-4: RES, 562 k, 1%, 0.1 W, 0603; Manufacturer: Yageo; Power_W: 100mW; TempCo: 100 ppm/C; Value: 562k; EIA_Code: E96; SizeX_mm: 1.6; SizeY_mm: 0.8; SizeZ_mm: 1; Value2: 0.1W; SizeArea_mm2: 1.28; AEC Qualified: N; VDC_V: 75V; AEC Category: Q200; SizeAreaWB_mm2: 4.68
R15 = CMP-0017552-3: RES, 3.48 k, 1%, 0.25 W, AEC-Q200 Grade 0, 1206; Manufacturer: Panasonic; Power_W: 250mW; TempCo: 100 ppm/C; Value_Code: 3k48; Value: 3.48k; EIA_Code: E96; SizeX_mm: 3.2; SizeY_mm: 1.6; SizeZ_mm: 1.35; Value2: 0.25W; SizeArea_mm2: 5.12; AEC Qualified: Y; VDC_V: 200V; AEC Category: Q200; AEC Grade: 0; SizeAreaWB_mm2: 10.92
R24 = CMP-0021770-3: RES, 6.65 k, 1%, 0.125 W, AEC-Q200 Grade 0, 0805; Manufacturer: Panasonic; Power_W: 125mW; TempCo: 100 ppm/C; Value_Code: 6k65; Value: 6.65k; EIA_Code: E96; SizeX_mm: 2; SizeY_mm: 1.25; SizeZ_mm: 1.45; Value2: 0.125W; SizeArea_mm2: 2.5; AEC Qualified: Y; AEC Category: Q200; AEC Grade: 0; SizeAreaWB_mm2: 6.75
R27 = CMP-0020843-1: RES, 10.2 k, 1%, 0.125 W, 0805; Manufacturer: Vishay-Dale; Power_W: 125mW; TempCo: 100 ppm/C; Value_Code: 10k2; U/M: EA; Value: 10.2k; EIA_Code: E96; SizeX_mm: 2; SizeY_mm: 1.25; SizeZ_mm: 1.45; Value2: 0.125W; SizeArea_mm2: 2.5; VDC_V: 150V; AEC Category: Q200
R36 = CMP-0023147-2: RES, 4.32 k, 1%, 0.1 W, 0603; Manufacturer: Yageo America; Power_W: 100mW; TempCo: 200 ppm/C; Value_Code: 4k32; U/M: EA; Value: 4.32k; EIA_Code: E96; SizeX_mm: 1.6; SizeY_mm: 0.8; SizeZ_mm: 1; Value2: 0.1W; SizeArea_mm2: 1.28; VDC_V: 150V; AEC Category: Q200
R500 = CMP-0026371-2: RES, 41.2 k, 1%, 0.063 W, AEC-Q200 Grade 0, 0402; Manufacturer: Vishay-Dale; Power_W: 63mW; TempCo: 100 ppm/C; Value_Code: 41k2; Value: 41.2k; EIA_Code: E96; SizeX_mm: 1; SizeY_mm: 0.5; SizeZ_mm: 0.6; Value2: 0.063W; AEC Qualified: Y; VDC_V: 50V; AEC Category: Q200; AEC Grade: 0
TP1 TP4-TP7 TP17 = CMP-0055138-1: Test Point, Miniature, Black, TH; Manufacturer: Keystone; CNHeader: FALSE; Green_Lifecycle: Active; Green_REACh: Passed; ContactFinish: Silver; CT: TRUE
U1 = CMP-0091061-1: 100-V Input, 3.5-A Non-Synchronous Buck DC/DC Converter with Ultra-low IQ; Manufacturer: Texas Instruments; AEC Qualified: Yes; Max Supply Voltage: 100V; Output Voltage: 1.2-90V; TaMax_C: +125°C; Standoff Height: 0mm; SizeZ_mm: 1.7mm; Max Duty Cycle: 100%; Min Supply Voltage: 6V; Nominal Supply Current: 300uA; Switching Frequency: 1MHz; Output Type: AdjustableProgrammable; Number Of Outputs: 1; AEC Grade: Grade 1; TJmax_C: +150°C; TaMin_C: -40°C
U2 U3 = CMP-0083641-1: TPS62130A-Q1 3 to 17-V 3-A Automotive Step-Down Converter in 3 × 3 QFN Package, RGT0016C (VQFN-16); Alternate PartNumber: TPS62130AQRGTRQ1; Alternate Manufacturer: Texas Instruments; SizeAreaWB_mm2: 16; SizeZ_mm: 1; SizeX_mm: 3; SizeArea_mm2: 9; CompType: IC; AEC Qualified: Y; AEC Category: Q200
U4 = CMP-0071334-1: 2MHz, 600mA Step-Down DC-DC Converter, 5-pin Micro SMD, Pb-Free; Manufacturer: Texas Instruments; High-Reliability: Y; PackageTopMarking: XV*I B; CompType: MiscPower
U6 = CMP-0051803-1: Automotive Catalog Dual 2-Input Positive-AND Gate, DCT0008A, LARGE T&R; Manufacturer: Texas Instruments; Generic Part Number: SN74LVC2G08-Q1; F @ Nom Voltage(Max)(Mhz): 150; ICC @ Nom Voltage(Max)(mA): 0.01; Input Type: CMOS/TTL; Output Type: CMOS; Logic: True; VCC(Max)(V): 5.5; Technology Family: LVC; Schmitt Trigger: No; Bits(#): 2; tpd @ Nom Voltage(Max)(ns): 9,5.1,4.7,3.8; VCC(Min)(V): 1.65; Voltage(Nom)(V): 1.8,2.5,3.3,5; Output Drive (IOL/IOH)(Max)(mA): 32/-32
U8 = CMP-0081409-1: Automotive Low-Quiescent-Current 1% Accurate Supervisor With Programmable Delay, DSE0006A (WSON-6); Alternate Manufacturer: Texas Instruments; SizeAreaWB_mm2: 6.25; SizeZ_mm: 0.8; SizeX_mm: 1.5; SizeArea_mm2: 2.25; CompType: IC; AEC Qualified: Y; AEC Category: Q200
U10 = CMP-0051598-1: Automotive Catalog Single 2-Input Positive-OR Gate, DBV0005A, LARGE T&R; Manufacturer: Texas Instruments; Output Type: CMOS; Bits(#): 1; Gate Type: OR; 3-State Output: No; VCC(Max)(V): 5.5; Voltage(Nom)(V): 3.3,5; Logic: True; tpd @ Nom Voltage(Max)(ns): 11.4,7.5; F @ Nom Voltage(Max)(Mhz): 75; Output Drive (IOL/IOH)(Max)(mA): 50/-50; Sub-Family: OR Gate; ICC @ Nom Voltage(Max)(mA): 0.01; Technology Family: AHC; VCC(Min)(V): 2
U11 = CMP-0750051-1: Overvoltage and Undervoltage Reset IC With Time Delay and Manual Reset, DSE0006A (WSON-6); Alternate Manufacturer: Texas Instruments; AEC Category: Q200; SizeY_mm: 1.5; AEC Qualified: Y; SizeAreaWB_mm2: 6.25; SizeZ_mm: 0.8; SizeArea_mm2: 2.25

## Sheet DLP096D_SoC_Power_Clock.SchDoc: SoC_Power & Clock
size 431 x 279 mm; Date: Not shown in title block; ApprovedBy: Not shown in title block; CheckedBy: Not shown in title block; Author: Not shown in title block; CompanyName: Not shown in title block; DrawnBy: A. Whitehead; Engineer: Not shown in title block; Organization: Not shown in title block; Address1: Not shown in title block; Address2: Not shown in title block; Address3: Not shown in title block; Address4: Not shown in title block; DocumentNumber: 4; Revision: Use project parameter SCH_Rev; SheetNumber: 4; SheetTotal: 10; PageSetup: Record=PageOptions¦CenterHorizontal=True¦CenterVertical=True¦PrintScale=1.00¦XCorrection=1.00¦YCorrection=1.00¦PrintKind=0¦BorderSize=5000000¦LeftOffset=0¦BottomOffset=0¦Orientation=2¦PaperLength=1000¦PaperWidth=1000¦Scale=100¦PaperSource=15¦PrintQuality=600¦MediaType=1¦DitherType=10¦PaperKind=Letter¦PrintScaleMode=1
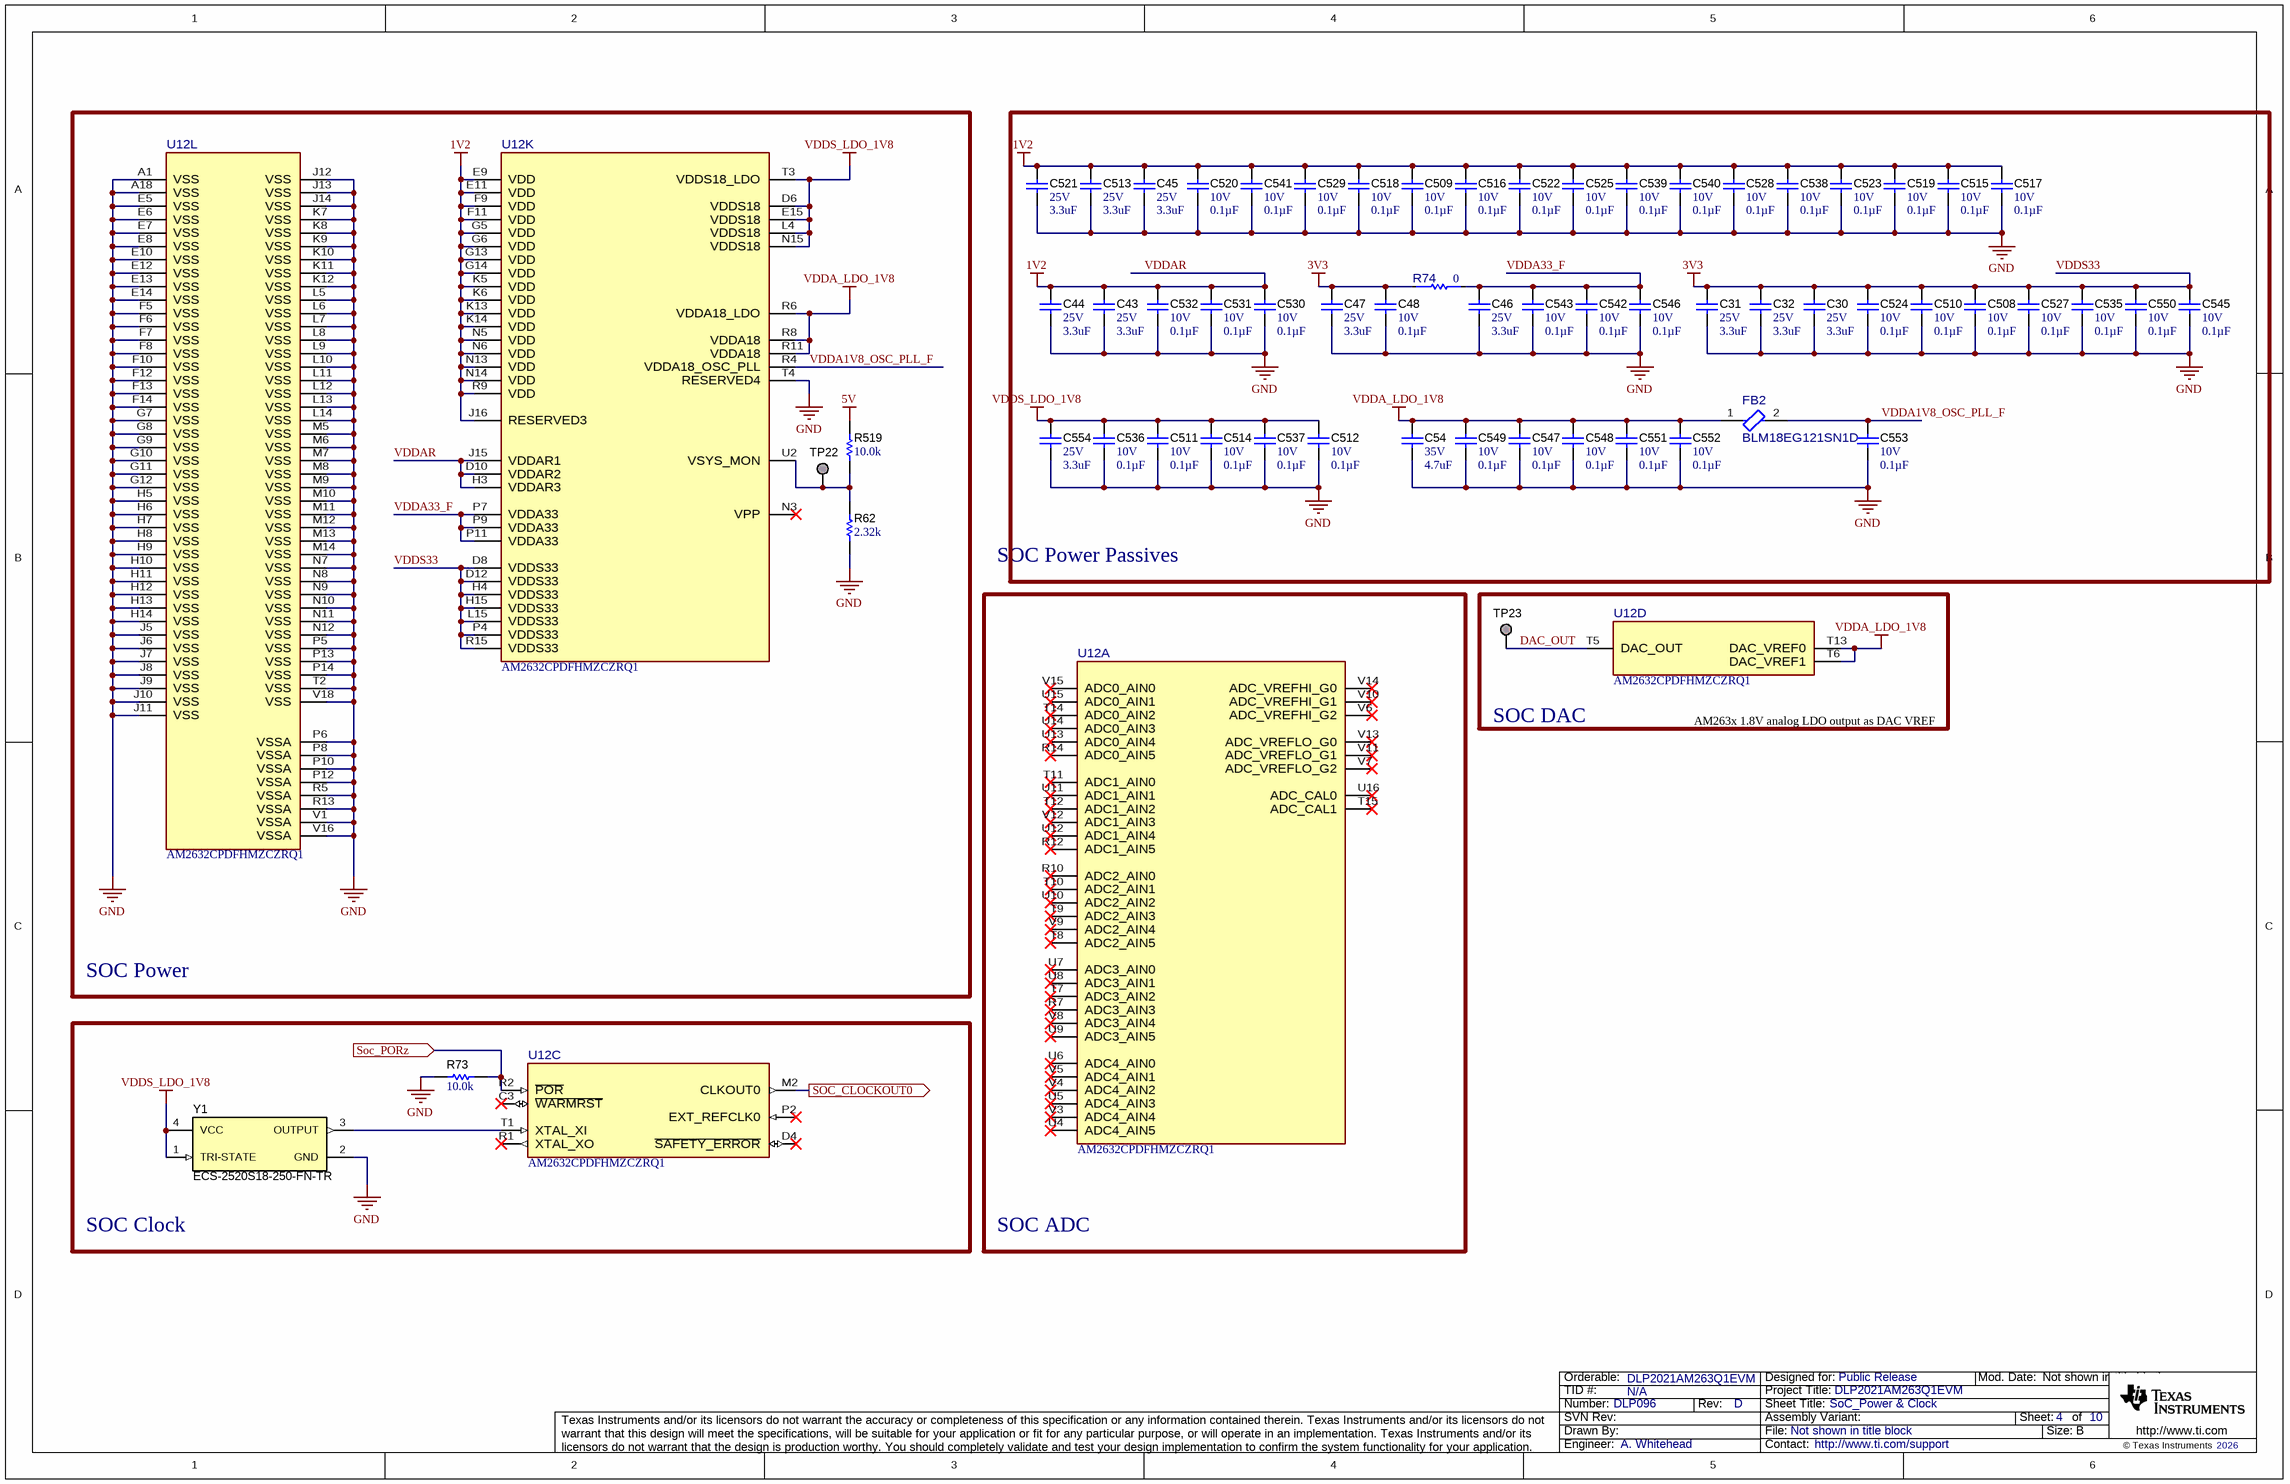
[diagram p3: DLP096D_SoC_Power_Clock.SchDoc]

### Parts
C30  VDC_V: 25V  ValueDisplayed: 3.3uF  [0603]  (hidden comment: C1608X5R1E335K080AC)
C31  VDC_V: 25V  ValueDisplayed: 3.3uF  [0603]  (hidden comment: C1608X5R1E335K080AC)
C32  VDC_V: 25V  ValueDisplayed: 3.3uF  [0603]  (hidden comment: C1608X5R1E335K080AC)
C43  VDC_V: 25V  ValueDisplayed: 3.3uF  [0603]  (hidden comment: C1608X5R1E335K080AC)
C44  VDC_V: 25V  ValueDisplayed: 3.3uF  [0603]  (hidden comment: C1608X5R1E335K080AC)
C45  VDC_V: 25V  ValueDisplayed: 3.3uF  [0603]  (hidden comment: C1608X5R1E335K080AC)
C46  VDC_V: 25V  ValueDisplayed: 3.3uF  [0603]  (hidden comment: C1608X5R1E335K080AC)
C47  VDC_V: 25V  ValueDisplayed: 3.3uF  [0603]  (hidden comment: C1608X5R1E335K080AC)
C48  VDC_V: 10V  ValueDisplayed: 0.1µF  [0201_033]  (hidden comment: GRM033R61A104KE84D)
C54  VDC_V: 35V  ValueDisplayed: 4.7uF  [0603]  (hidden comment: C1608X5R1V475K080AC)
C508  VDC_V: 10V  ValueDisplayed: 0.1µF  [0201_033]  (hidden comment: GRM033R61A104KE84D)
C509  VDC_V: 10V  ValueDisplayed: 0.1µF  [0201_033]  (hidden comment: GRM033R61A104KE84D)
C510  VDC_V: 10V  ValueDisplayed: 0.1µF  [0201_033]  (hidden comment: GRM033R61A104KE84D)
C511  VDC_V: 10V  ValueDisplayed: 0.1µF  [0201_033]  (hidden comment: GRM033R61A104KE84D)
C512  VDC_V: 10V  ValueDisplayed: 0.1µF  [0201_033]  (hidden comment: GRM033R61A104KE84D)
C513  VDC_V: 25V  ValueDisplayed: 3.3uF  [0603]  (hidden comment: C1608X5R1E335K080AC)
C514  VDC_V: 10V  ValueDisplayed: 0.1µF  [0201_033]  (hidden comment: GRM033R61A104KE84D)
C515  VDC_V: 10V  ValueDisplayed: 0.1µF  [0201_033]  (hidden comment: GRM033R61A104KE84D)
C516  VDC_V: 10V  ValueDisplayed: 0.1µF  [0201_033]  (hidden comment: GRM033R61A104KE84D)
C517  VDC_V: 10V  ValueDisplayed: 0.1µF  [0201_033]  (hidden comment: GRM033R61A104KE84D)
C518  VDC_V: 10V  ValueDisplayed: 0.1µF  [0201_033]  (hidden comment: GRM033R61A104KE84D)
C519  VDC_V: 10V  ValueDisplayed: 0.1µF  [0201_033]  (hidden comment: GRM033R61A104KE84D)
C520  VDC_V: 10V  ValueDisplayed: 0.1µF  [0201_033]  (hidden comment: GRM033R61A104KE84D)
C521  VDC_V: 25V  ValueDisplayed: 3.3uF  [0603]  (hidden comment: C1608X5R1E335K080AC)
C522  VDC_V: 10V  ValueDisplayed: 0.1µF  [0201_033]  (hidden comment: GRM033R61A104KE84D)
C523  VDC_V: 10V  ValueDisplayed: 0.1µF  [0201_033]  (hidden comment: GRM033R61A104KE84D)
C524  VDC_V: 10V  ValueDisplayed: 0.1µF  [0201_033]  (hidden comment: GRM033R61A104KE84D)
C525  VDC_V: 10V  ValueDisplayed: 0.1µF  [0201_033]  (hidden comment: GRM033R61A104KE84D)
C527  VDC_V: 10V  ValueDisplayed: 0.1µF  [0201_033]  (hidden comment: GRM033R61A104KE84D)
C528  VDC_V: 10V  ValueDisplayed: 0.1µF  [0201_033]  (hidden comment: GRM033R61A104KE84D)
C529  VDC_V: 10V  ValueDisplayed: 0.1µF  [0201_033]  (hidden comment: GRM033R61A104KE84D)
C530  VDC_V: 10V  ValueDisplayed: 0.1µF  [0201_033]  (hidden comment: GRM033R61A104KE84D)
C531  VDC_V: 10V  ValueDisplayed: 0.1µF  [0201_033]  (hidden comment: GRM033R61A104KE84D)
C532  VDC_V: 10V  ValueDisplayed: 0.1µF  [0201_033]  (hidden comment: GRM033R61A104KE84D)
C535  VDC_V: 10V  ValueDisplayed: 0.1µF  [0201_033]  (hidden comment: GRM033R61A104KE84D)
C536  VDC_V: 10V  ValueDisplayed: 0.1µF  [0201_033]  (hidden comment: GRM033R61A104KE84D)
C537  VDC_V: 10V  ValueDisplayed: 0.1µF  [0201_033]  (hidden comment: GRM033R61A104KE84D)
C538  VDC_V: 10V  ValueDisplayed: 0.1µF  [0201_033]  (hidden comment: GRM033R61A104KE84D)
C539  VDC_V: 10V  ValueDisplayed: 0.1µF  [0201_033]  (hidden comment: GRM033R61A104KE84D)
C540  VDC_V: 10V  ValueDisplayed: 0.1µF  [0201_033]  (hidden comment: GRM033R61A104KE84D)
C541  VDC_V: 10V  ValueDisplayed: 0.1µF  [0201_033]  (hidden comment: GRM033R61A104KE84D)
C542  VDC_V: 10V  ValueDisplayed: 0.1µF  [0201_033]  (hidden comment: GRM033R61A104KE84D)
C543  VDC_V: 10V  ValueDisplayed: 0.1µF  [0201_033]  (hidden comment: GRM033R61A104KE84D)
C545  VDC_V: 10V  ValueDisplayed: 0.1µF  [0201_033]  (hidden comment: GRM033R61A104KE84D)
C546  VDC_V: 10V  ValueDisplayed: 0.1µF  [0201_033]  (hidden comment: GRM033R61A104KE84D)
C547  VDC_V: 10V  ValueDisplayed: 0.1µF  [0201_033]  (hidden comment: GRM033R61A104KE84D)
C548  VDC_V: 10V  ValueDisplayed: 0.1µF  [0201_033]  (hidden comment: GRM033R61A104KE84D)
C549  VDC_V: 10V  ValueDisplayed: 0.1µF  [0201_033]  (hidden comment: GRM033R61A104KE84D)
C550  VDC_V: 10V  ValueDisplayed: 0.1µF  [0201_033]  (hidden comment: GRM033R61A104KE84D)
C551  VDC_V: 10V  ValueDisplayed: 0.1µF  [0201_033]  (hidden comment: GRM033R61A104KE84D)
C552  VDC_V: 10V  ValueDisplayed: 0.1µF  [0201_033]  (hidden comment: GRM033R61A104KE84D)
C553  VDC_V: 10V  ValueDisplayed: 0.1µF  [0201_033]  (hidden comment: GRM033R61A104KE84D)
C554  VDC_V: 25V  ValueDisplayed: 3.3uF  [0603]  (hidden comment: C1608X5R1E335K080AC)
FB2  BLM18EG121SN1D  [FP-BLM18EG121SN1D_0603-MFG]
R62  ValueDisplayed: 2.32k  [0402]  (hidden comment: CRCW04022K32FKED)
R73  ValueDisplayed: 10.0k  [0402]  (hidden comment: CRCW040210K0FKED)
R74  Res_ohm: 0  [FP-RMCF0805ZT0R00_0805-IPC_C]  (hidden comment: RMCF0805ZT0R00)
R519  ValueDisplayed: 10.0k  [0402]  (hidden comment: CRCW040210K0FKED)
TP22  TP_H0.45P0.75  [TP_H045P075]  (value not drawn)  (no BOM)
TP23  DAC_OUT  [TP_H045P075]  (value not drawn)  (no BOM)
U12  PartNumber: AM2632CPDFHMZCZRQ1  [ZCZ0324A-MFG]  (hidden comment: XAM2634AOLFGMZCZQ)  (parts A,C,D,K,L of 13)
Y1  ECS-2520S18-250-FN-TR  [ECS_ECS-2520S]

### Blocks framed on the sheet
SOC Power: R62 R519 TP22 U12
SOC ADC: U12
SOC DAC: TP23 U12
SOC Clock: R73 U12 Y1

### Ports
SOC_CLOCKOUT0 (out), Soc_PORz (in)

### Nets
5V: R519.2
GND: C30.2 C31.2 C32.2 C43.2 C44.2 C45.2 C46.2 C47.2 C48.2 C54.2 C508.2 C509.2 C510.2 C511.2 C512.2 C513.2 C514.2 C515.2 C516.2 C517.2 C518.2 C519.2 C520.2 C521.2 C522.2 C523.2 C524.2 C525.2 C527.2 C528.2 C529.2 C530.2 C531.2 C532.2 C535.2 C536.2 C537.2 C538.2 C539.2 C540.2 C541.2 C542.2 C543.2 C545.2 C546.2 C547.2 C548.2 C549.2 C550.2 C551.2 C552.2 C553.2 C554.2 R62.1 R73.2 U12.A1(VSS) U12.A18(VSS) U12.E5(VSS) U12.E6(VSS) U12.E7(VSS) U12.E8(VSS) U12.E10(VSS) U12.E12(VSS) U12.E13(VSS) U12.E14(VSS) U12.F5(VSS) U12.F6(VSS) U12.F7(VSS) U12.F8(VSS) U12.F10(VSS) U12.F12(VSS) U12.F13(VSS) U12.F14(VSS) U12.G7(VSS) U12.G8(VSS) U12.G9(VSS) U12.G10(VSS) U12.G11(VSS) U12.G12(VSS) U12.H5(VSS) U12.H6(VSS) U12.H7(VSS) U12.H8(VSS) U12.H9(VSS) U12.H10(VSS) U12.H11(VSS) U12.H12(VSS) U12.H13(VSS) U12.H14(VSS) U12.J5(VSS) U12.J6(VSS) U12.J7(VSS) U12.J8(VSS) U12.J9(VSS) U12.J10(VSS) U12.J11(VSS) U12.J12(VSS) U12.J13(VSS) U12.J14(VSS) U12.K7(VSS) U12.K8(VSS) U12.K9(VSS) U12.K10(VSS) U12.K11(VSS) U12.K12(VSS) U12.L5(VSS) U12.L6(VSS) U12.L7(VSS) U12.L8(VSS) U12.L9(VSS) U12.L10(VSS) U12.L11(VSS) U12.L12(VSS) U12.L13(VSS) U12.L14(VSS) U12.M5(VSS) U12.M6(VSS) U12.M7(VSS) U12.M8(VSS) U12.M9(VSS) U12.M10(VSS) U12.M11(VSS) U12.M12(VSS) U12.M13(VSS) U12.M14(VSS) U12.N7(VSS) U12.N8(VSS) U12.N9(VSS) U12.N10(VSS) U12.N11(VSS) U12.N12(VSS) U12.P5(VSS) U12.P6(VSSA) U12.P8(VSSA) U12.P10(VSSA) U12.P12(VSSA) U12.P13(VSS) U12.P14(VSS) U12.R5(VSSA) U12.R13(VSSA) U12.T2(VSS) U12.T4(RESERVED4) U12.V1(VSSA) U12.V16(VSSA) U12.V18(VSS) Y1.2(GND)
VDDA_LDO_1V8: C54.1 C547.1 C548.1 C549.1 C551.1 C552.1 FB2.1 U12.R6(VDDA18_LDO) U12.R8(VDDA18) U12.R11(VDDA18) U12.T6(DAC_VREF1) U12.T13(DAC_VREF0)
VDDAR: C43.1 C44.1 C45.1 C509.1 C513.1 C515.1 C516.1 C517.1 C518.1 C519.1 C520.1 C521.1 C522.1 C523.1 C525.1 C528.1 C529.1 C530.1 C531.1 C532.1 C538.1 C539.1 C540.1 C541.1 U12.D10(VDDAR2) U12.E9(VDD) U12.E11(VDD) U12.F9(VDD) U12.F11(VDD) U12.G5(VDD) U12.G6(VDD) U12.G13(VDD) U12.G14(VDD) U12.H3(VDDAR3) U12.J15(VDDAR1) U12.J16(RESERVED3) U12.K5(VDD) U12.K6(VDD) U12.K13(VDD) U12.K14(VDD) U12.N5(VDD) U12.N6(VDD) U12.N13(VDD) U12.N14(VDD) U12.R9(VDD)  [also labelled 1V2]
VDDS33: C30.1 C31.1 C32.1 C47.1 C48.1 C508.1 C510.1 C524.1 C527.1 C535.1 C545.1 C550.1 R74.1 U12.D8(VDDS33) U12.D12(VDDS33) U12.H4(VDDS33) U12.H15(VDDS33) U12.L15(VDDS33) U12.P4(VDDS33) U12.R15(VDDS33)  [also labelled 3V3]
VDDS_LDO_1V8: C511.1 C512.1 C514.1 C536.1 C537.1 C554.1 U12.D6(VDDS18) U12.E15(VDDS18) U12.L4(VDDS18) U12.N15(VDDS18) U12.T3(VDDS18_LDO) Y1.1(TRI-STATE) Y1.4(VCC)
DAC_OUT: TP23.1 U12.T5(DAC_OUT)
SOC_CLOCKOUT0: U12.M2(CLKOUT0) ; port SOC_CLOCKOUT0
Soc_PORz: R73.1 U12.R2(~{POR}) ; port Soc_PORz
VDDA1V8_OSC_PLL_F: C553.1 FB2.2 U12.R4(VDDA18_OSC_PLL)
VDDA33_F: C46.1 C542.1 C543.1 C546.1 R74.2 U12.P7(VDDA33) U12.P9(VDDA33) U12.P11(VDDA33)
NetR62_2: R62.2 R519.1 TP22.1 U12.U2(VSYS_MON)
NetU12_T1: U12.T1(XTAL_XI) Y1.3(OUTPUT)

Not connected (* = marked no-connect by the designer): U12 C3(~{WARMRST})* D4(~{SAFETY_ERROR})* N3(VPP)* P2(EXT_REFCLK0)* R1(XTAL_XO)* R7(ADC3_AIN3)* R10(ADC2_AIN0)* R12(ADC1_AIN5)* R14(ADC0_AIN5)* T7(ADC3_AIN2)* T8(ADC2_AIN5)* T9(ADC2_AIN3)* T10(ADC2_AIN1)* T11(ADC1_AIN0)* T12(ADC1_AIN2)* T14(ADC0_AIN2)* T15(ADC_CAL1)* U4(ADC4_AIN5)* U5(ADC4_AIN3)* U6(ADC4_AIN0)* U7(ADC3_AIN0)* U8(ADC3_AIN1)* U9(ADC3_AIN5)* U10(ADC2_AIN2)* U11(ADC1_AIN1)* U12(ADC1_AIN4)* U13(ADC0_AIN4)* U14(ADC0_AIN3)* U15(ADC0_AIN1)* U16(ADC_CAL0)* V3(ADC4_AIN4)* V4(ADC4_AIN2)* V5(ADC4_AIN1)* V6(ADC_VREFHI_G2)* V7(ADC_VREFLO_G2)* V8(ADC3_AIN4)* V9(ADC2_AIN4)* V10(ADC_VREFHI_G1)* V11(ADC_VREFLO_G1)* V12(ADC1_AIN3)* V13(ADC_VREFLO_G0)* V14(ADC_VREFHI_G0)* V15(ADC0_AIN0)*

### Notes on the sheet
- SOC Power Passives
- (near U12) AM263x 1.8V analog LDO output as DAC VREF

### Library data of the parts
C30-C32 C43-C47 C513 C521 C554 = CMP-0007008-1: CAP, CERM, 3.3 uF, 25 V, +/- 10%, X5R, 0603; Manufacturer: TDK; TaMin_C: -55°C; Polarized: N; SizeAreaWB_mm2: 4.68; Value1: Unknown; U/M: EA; Value: 3.3uF; TaMax_C: 85°C; SizeZ_mm: 1; SizeX_mm: 1.6; SizeY_mm: 0.8; SizeArea_mm2: 1.28; Cap_F: 3.3µF; AEC Category: Q200
C48 C508-C512 C514-C520 C522-C525 C527-C532 C535-C543 C545-C553 = CMP-0086059-1: CAP, CERM, 0.1 µF, 10 V,+/- 10%, X5R, 0201; Manufacturer: MuRata; AEC Category: Q200; Cap_F: 100nF; Value: 0.1uF; SizeY_mm: 0.3; AEC Qualified: N; SizeAreaWB_mm2: 2.08; Cap_Case: 0201; SizeArea_mm2: 0.18; SizeZ_mm: 0.33; SizeX_mm: 0.6; TaMax_C: 85°C; TaMin_C: -55°C; U/M: EA
C54 = CMP-0007022-5: CAP, CERM, 4.7 uF, 35 V, +/- 10%, X5R, 0603; Manufacturer: TDK; TaMin_C: -55°C; ESR_ohm: 3.728m; Polarized: N; SizeAreaWB_mm2: 4.68; Value1: 0.003728 ohm; U/M: EA; Value: 4.7uF; TaMax_C: 85°C; SizeZ_mm: 1; SizeX_mm: 1.6; SizeY_mm: 0.8; SizeArea_mm2: 1.28; Cap_F: 4.7µF; IRMS_A: 2.6936A; AEC Category: Q200
FB2 = CMP-0089199-1: 120 Ohms @ 100MHz 1  Ferrite Bead 0603 (1608 Metric) 2A 40mOhm; Manufacturer: Murata; DCR_ohm: 60m; AEC Qualified: No; Tolerance_%: 25%; SizeZ_mm: 0.95mm; Impedance At Frequency: 120Ω @ 100MHz
R62 = CMP-0026240-2: RES, 2.32 k, 1%, 0.063 W, AEC-Q200 Grade 0, 0402; Manufacturer: Vishay-Dale; Power_W: 63mW; TempCo: 100 ppm/C; Value_Code: 2k32; Value: 2.32k; EIA_Code: E96; Res_ohm: 2.67k; SizeX_mm: 1; SizeY_mm: 0.5; SizeZ_mm: 0.6; Value2: 0.063W; AEC Qualified: Y; VDC_V: 50V; AEC Category: Q200; AEC Grade: 0
R73 R519 = CMP-0025958-2: RES, 10.0 k, 1%, 0.063 W, 0402; Manufacturer: Vishay-Dale; Power_W: 63mW; TempCo: 100 ppm/C; Value_Code: 10k0; U/M: EA; Value: 10.0k; EIA_Code: E96; Res_ohm: 10k; SizeX_mm: 1; SizeY_mm: 0.5; SizeZ_mm: 0.6; Value2: 0.063W; VDC_V: 50V; AEC Category: Q200
R74 = CMP-0089632-1: 0 Ohms Jumper 0.125W, 1/8W Chip Resistor 0805 (2012 Metric) Automotive AEC-Q200 Thick Film; Manufacturer: Stackpole Electronics; SizeZ_mm: 0.65mm; Power_W: 125mW; AEC Grade: Grade 0; AEC Qualified: Yes; TempCo: 200ppm/°C; VDC_V: 150V
TP22 = CMP-0003719-1: Testpoint; Manufacturer: Texas Instruments; CompType: Pad
TP23 = CMP-0003719-1: Testpoint; Manufacturer: Texas Instruments; Key: TP_H0.45P0.75; CompType: Pad
U12 = CMP-0093674-1: Sitara™ Microcontrollers; Manufacturer: Texas Instruments; Min Supply Voltage: 1.14V; Number Of Adc Channels: 30; AEC Qualified: No; TJmax_C: +105°C; Memory Type: SRAM; Standoff Height: 0.35mm; Core Architecture: ARM Cortex-R5F; Number Of I2C Channels: 4; Number Of Pwm Channels: 24; Number Of Spi Channels: 5; Number Of Cores: 2; Frequency_Fixed: 400MHz; Nominal Supply Current: 200-2500mA; Ram Size: 2MBytes; Number Of Ethernet Channels: 1; Interface: I2C,SPI,UART,CAN,LIN,Ethernet,Other; Data Bus Width: 64bits; SizeZ_mm: 1.4mm; Number Of Uart Channels: 6; Number Of I/Os: 140; Max Supply Voltage: 3.465V
Y1 = CMP-0082061-2: Oscillator, 25 MHz, 15 pF, SMD; Manufacturer: ECS Inc.; SizeAreaWB_mm2: 10.5; Frequency Stability: 10 ppm; SizeY_mm: 2.5; SizeZ_mm: 1; AEC Category: Q200; TaMax_C: 85°C; Load Capacitance: 15 pF; AEC Qualified: N; SizeX_mm: 2; TaMin_C: -40°C; Frequency_Fixed: 25MHz; SizeArea_mm2: 5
